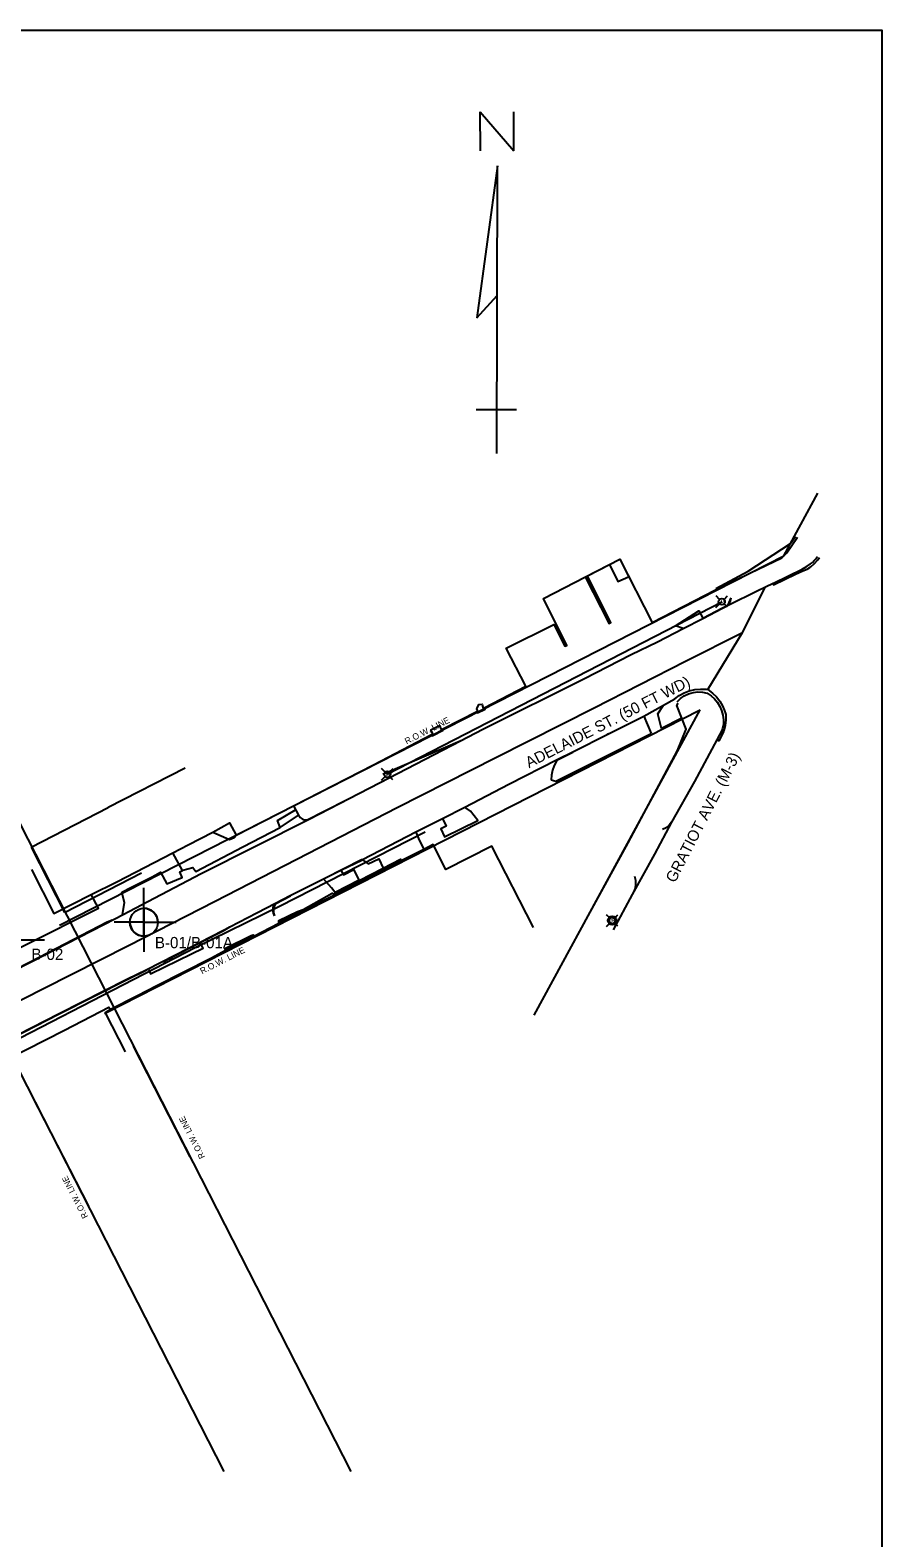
# Model space of a CAD drawing. Extents: x 19007.1 to 19038.2, y 21497.8 to 21516.9.
# Drawn here: x 19030.01 to 19036.42, y 21505.53 to 21516.88 of the extents above; entities that cross this region are included whole.
import ezdxf

# ---------------------------------------------------------------- set-up
doc = ezdxf.new("R2010")
doc.units = 0
for name, color, linetype in [('BORDER', 7, 'Continuous'), ('DETAIL_TEXT_DIMEN_PR', 7, 'Continuous'), ('G-ANNO-TTLB', 7, 'Continuous'), ('Level 14', 7, 'Continuous'), ('TYPICAL_TEXT_DIMEN_PR', 7, 'Continuous'), ('V-ANNO-TEXT', 7, 'Continuous'), ('V-BLDG-OTLN', 7, 'Continuous'), ('V-DEMO-PVMT', 7, 'Continuous'), ('V-PROP-RWAY', 7, 'Continuous'), ('V-PROP-RWAY-IDEN', 7, 'Continuous'), ('V-PVMT-CNTR', 7, 'Continuous'), ('V-PVMT-ROAD', 7, 'Continuous'), ('V-SITE-FENC', 7, 'Continuous'), ('V-SITE-STRS', 7, 'Continuous'), ('V-SITE-WALK', 7, 'Continuous'), ('V-UTIL-OVHD', 7, 'Continuous')]:
    doc.layers.add(name, color=color, linetype=linetype)

msp = doc.modelspace()

# ---------------------------------------------------------------- linework, layer by layer
at = {"layer": 'BORDER'}
for p, q in [((19033.402, 21515.972), (19033.399, 21516.267)), ((19033.399, 21516.267), (19033.653, 21515.971)), ((19033.653, 21515.971), (19033.652, 21516.267)), ((19033.528, 21515.86), (19033.374, 21514.715)), ((19033.523, 21513.693), (19033.528, 21515.86)), ((19033.374, 21514.715), (19033.526, 21514.882)), ((19033.673, 21514.021), (19033.368, 21514.022))]:
    msp.add_line(p, q, dxfattribs=at)
at = {"layer": 'G-ANNO-TTLB'}
msp.add_lwpolyline([(19036.423, 21497.766), (19007.08, 21497.766), (19007.08, 21516.881), (19036.423, 21516.881)], close=True, dxfattribs=at)
at = {"layer": 'Level 14'}
msp.add_circle((19034.393, 21510.176), 0.0328, dxfattribs=at)
at = {"layer": 'TYPICAL_TEXT_DIMEN_PR'}
for p, q in [((19030.866, 21510.163), (19030.866, 21510.421)), ((19030.866, 21510.163), (19030.642, 21510.163)), ((19030.866, 21510.163), (19030.866, 21509.939)), ((19030.866, 21510.163), (19031.11, 21510.163)), ((19029.874, 21510.031), (19030.118, 21510.031))]:
    msp.add_line(p, q, dxfattribs=at)
for points in [[(19030.866, 21510.268), (19030.866, 21510.163), (19030.971, 21510.163)], [(19030.866, 21510.057), (19030.866, 21510.163), (19030.76, 21510.163)]]:
    msp.add_lwpolyline(points, dxfattribs=at)
msp.add_circle((19030.866, 21510.163), 0.105, dxfattribs=at)
for start, end in [(0.0399, 90.0399), (180.0399, 270.0399)]:
    msp.add_arc((19030.866, 21510.163), 0.105, start, end, dxfattribs=at)
at = {"layer": 'V-BLDG-OTLN'}
for points in [[(19030.019, 21510.561), (19030.188, 21510.23), (19030.468, 21510.372), (19030.663, 21510.468), (19031.085, 21510.686), (19031.2, 21510.746), (19031.384, 21510.842), (19031.511, 21510.911), (19031.56, 21510.819), (19031.993, 21511.039), (19032.596, 21511.349), (19033.033, 21511.577), (19033.042, 21511.583), (19033.028, 21511.612), (19033.091, 21511.645), (19033.097, 21511.633), (19033.097, 21511.632), (19033.104, 21511.615), (19033.115, 21511.616), (19033.116, 21511.619), (19033.372, 21511.75), (19033.379, 21511.755), (19033.379, 21511.758), (19033.373, 21511.77), (19033.372, 21511.771), (19033.388, 21511.802), (19033.414, 21511.805), (19033.415, 21511.792), (19033.415, 21511.791), (19033.42, 21511.776), (19033.429, 21511.778), (19033.743, 21511.94), (19033.595, 21512.227), (19033.954, 21512.405), (19034.037, 21512.242), (19034.051, 21512.248), (19033.875, 21512.602), (19034.191, 21512.763), (19034.45, 21512.896), (19034.694, 21512.421), (19035.171, 21512.665)], [(19034.204, 21512.77), (19034.379, 21512.42), (19034.371, 21512.415), (19034.366, 21512.421), (19034.194, 21512.76)], [(19033.8, 21510.124), (19033.487, 21510.736), (19033.14, 21510.561), (19033.045, 21510.748), (19032.973, 21510.712), (19032.804, 21510.626), (19032.31, 21510.373), (19032.301, 21510.368), (19032.033, 21510.231), (19031.893, 21510.158), (19031.881, 21510.153), (19031.695, 21510.056), (19031.681, 21510.049), (19031.486, 21509.952), (19031.369, 21509.889), (19030.964, 21509.683), (19030.819, 21509.609), (19030.614, 21509.505), (19030.574, 21509.482), (19030.725, 21509.186)], [(19032.31, 21510.373), (19032.304, 21510.384), (19032.488, 21510.478), (19032.667, 21510.571), (19032.799, 21510.639), (19032.804, 21510.626)], [(19031.893, 21510.158), (19031.887, 21510.172), (19032.024, 21510.241), (19032.033, 21510.231)], [(19031.486, 21509.952), (19031.478, 21509.964), (19031.675, 21510.06), (19031.681, 21510.049)]]:
    msp.add_lwpolyline(points, dxfattribs=at)
at = {"layer": 'V-DEMO-PVMT'}
for points in [[(19028.097, 21508.889), (19028.362, 21509.022), (19028.49, 21509.087), (19028.616, 21509.152), (19029.3, 21509.501), (19030.016, 21509.866), (19030.652, 21510.19), (19030.704, 21510.219), (19030.996, 21510.373)], [(19028.108, 21509.039), (19028.353, 21509.164), (19028.617, 21509.301), (19029.241, 21509.619), (19029.408, 21509.702), (19029.965, 21509.988), (19030.523, 21510.268), (19030.468, 21510.372)], [(19030.701, 21510.39), (19030.772, 21510.426)], [(19030.704, 21510.219), (19030.719, 21510.312), (19030.701, 21510.39)], [(19028.555, 21509.213), (19028.585, 21509.187), (19028.628, 21509.161), (19029.299, 21509.504), (19030.015, 21509.868), (19030.59, 21510.166), (19030.626, 21510.182)], [(19028.305, 21508.482), (19028.718, 21508.689), (19029.272, 21508.987), (19029.505, 21509.106), (19030.229, 21509.475), (19030.738, 21509.734), (19030.887, 21509.807), (19031.202, 21509.968)], [(19030.903, 21509.805), (19030.917, 21509.774), (19031.224, 21509.925)], [(19031.01, 21509.866), (19031.203, 21509.965)], [(19029.262, 21508.846), (19029.258, 21508.867), (19029.265, 21508.958), (19029.277, 21508.987), (19029.507, 21509.104), (19030.228, 21509.473), (19030.74, 21509.732), (19030.888, 21509.804)]]:
    msp.add_lwpolyline(points, dxfattribs=at)
at = {"layer": 'V-PROP-RWAY'}
for p, q in [((19035.684, 21512.923), (19035.94, 21513.393)), ((19031.47, 21506.028), (19027.81, 21513.188)), ((19028.765, 21513.188), (19032.424, 21506.028)), ((19030.231, 21510.14), (19035.684, 21512.923)), ((19030.57, 21509.475), (19035.054, 21511.763)), ((19033.804, 21509.464), (19035.054, 21511.763)), ((19032.666, 21511.278), (19033.266, 21511.536)), ((19031.177, 21511.324), (19030.597, 21511.027)), ((19030.017, 21510.729), (19030.597, 21511.027)), ((19030.017, 21510.729), (19030.269, 21510.237)), ((19030.269, 21510.237), (19030.849, 21510.535)), ((19031.214, 21508.396), (19030.787, 21509.229)), ((19030.022, 21508.857), (19030.448, 21508.024))]:
    msp.add_line(p, q, dxfattribs=at)
at = {"layer": 'V-PVMT-CNTR'}
msp.add_lwpolyline([(19024.711, 21506.912), (19025.192, 21507.157), (19025.429, 21507.272), (19025.614, 21507.374), (19025.854, 21507.494), (19026.581, 21507.868), (19027.297, 21508.234), (19027.984, 21508.583), (19028.701, 21508.941), (19029.396, 21509.302), (19030.11, 21509.663), (19030.749, 21509.989), (19031.403, 21510.322), (19032.101, 21510.681), (19032.774, 21511.026), (19033.516, 21511.404), (19034.256, 21511.778), (19034.944, 21512.128), (19035.373, 21512.345)], dxfattribs=at)
at = {"layer": 'V-PVMT-ROAD'}
for points in [[(19030.996, 21510.373), (19031.298, 21510.531), (19032.11, 21510.939), (19032.412, 21511.094), (19032.639, 21511.213), (19033.187, 21511.496), (19033.424, 21511.619), (19034.179, 21511.995), (19034.536, 21512.178), (19034.733, 21512.275), (19034.927, 21512.374), (19035.075, 21512.451), (19035.271, 21512.553), (19035.484, 21512.658), (19035.546, 21512.689), (19035.604, 21512.716), (19035.607, 21512.705), (19035.773, 21512.784), (19035.829, 21512.81), (19035.861, 21512.823), (19035.88, 21512.834), (19035.892, 21512.843), (19035.914, 21512.862), (19035.941, 21512.893), (19035.953, 21512.91)], [(19034.191, 21512.763), (19034.367, 21512.412), (19034.382, 21512.42), (19034.207, 21512.771), (19034.373, 21512.856), (19034.436, 21512.728), (19034.516, 21512.764)], [(19035.606, 21512.717), (19035.823, 21512.821), (19035.854, 21512.84), (19035.886, 21512.861), (19035.901, 21512.873), (19035.914, 21512.887), (19035.923, 21512.897), (19035.938, 21512.918)], [(19035.074, 21512.453), (19035.265, 21512.552), (19035.289, 21512.606)], [(19035.113, 21511.915), (19035.373, 21512.345), (19035.546, 21512.689)], [(19035.272, 21512.556), (19035.284, 21512.583), (19035.289, 21512.606)], [(19031.202, 21509.968), (19031.289, 21510.013), (19031.461, 21510.101), (19031.514, 21510.128), (19031.716, 21510.234), (19031.857, 21510.307), (19031.968, 21510.364), (19032.219, 21510.49), (19032.229, 21510.494), (19032.504, 21510.635), (19032.512, 21510.635), (19032.915, 21510.843), (19033.115, 21510.945), (19033.283, 21511.029), (19033.613, 21511.202), (19033.979, 21511.388), (19034.096, 21511.447), (19034.364, 21511.582), (19034.354, 21511.577), (19034.63, 21511.716), (19034.78, 21511.797), (19034.863, 21511.845), (19034.897, 21511.87), (19034.934, 21511.891), (19034.973, 21511.906), (19035.014, 21511.916), (19035.057, 21511.919), (19035.099, 21511.917), (19035.113, 21511.915), (19035.148, 21511.889), (19035.178, 21511.861), (19035.203, 21511.828), (19035.223, 21511.793), (19035.235, 21511.763), (19035.248, 21511.728), (19035.249, 21511.686), (19035.244, 21511.644), (19035.233, 21511.602), (19035.232, 21511.601), (19035.195, 21511.529), (19035.183, 21511.537)], [(19034.881, 21511.822), (19034.906, 21511.848), (19034.935, 21511.868), (19034.967, 21511.884), (19035.001, 21511.894), (19035.037, 21511.898), (19035.072, 21511.896), (19035.107, 21511.889), (19035.107, 21511.889), (19035.137, 21511.868), (19035.164, 21511.845), (19035.186, 21511.818), (19035.204, 21511.787), (19035.215, 21511.757), (19035.226, 21511.722), (19035.231, 21511.688), (19035.23, 21511.655), (19035.223, 21511.622), (19035.218, 21511.607), (19035.011, 21511.223), (19034.84, 21510.916), (19034.712, 21510.675), (19034.544, 21510.372), (19034.401, 21510.107)], [(19034.354, 21511.577), (19034.631, 21511.714), (19034.687, 21511.585)], [(19034.917, 21511.699), (19034.764, 21511.623), (19034.735, 21511.732), (19034.78, 21511.797)], [(19033.033, 21511.577), (19033.038, 21511.567), (19033.12, 21511.61)], [(19033.98, 21511.386), (19034.096, 21511.445)], [(19031.893, 21510.876), (19031.871, 21510.928), (19032.007, 21511.01)], [(19031.993, 21511.039), (19032.03, 21510.97), (19032.032, 21510.966), (19032.043, 21510.952), (19032.057, 21510.941), (19032.074, 21510.935), (19032.092, 21510.935), (19032.1, 21510.937), (19032.219, 21510.996), (19032.412, 21511.094)], [(19033.115, 21510.945), (19033.143, 21510.887), (19033.101, 21510.867), (19033.13, 21510.806), (19033.38, 21510.929), (19033.326, 21510.999), (19033.292, 21511.022), (19033.283, 21511.029)], [(19031.159, 21510.556), (19031.234, 21510.575), (19031.258, 21510.545), (19031.611, 21510.732), (19031.893, 21510.876), (19032.03, 21510.97)], [(19034.84, 21510.916), (19034.821, 21510.894), (19034.798, 21510.875), (19034.772, 21510.862)], [(19031.384, 21510.842), (19031.51, 21510.786), (19031.545, 21510.8), (19031.56, 21510.819)], [(19032.916, 21510.836), (19032.934, 21510.793), (19032.973, 21510.712)], [(19030.928, 21510.506), (19030.992, 21510.539), (19031.038, 21510.451), (19031.153, 21510.501), (19031.136, 21510.543), (19031.157, 21510.553), (19031.085, 21510.686)], [(19032.229, 21510.494), (19032.348, 21510.554), (19032.513, 21510.633)], [(19032.306, 21510.389), (19032.486, 21510.482), (19032.448, 21510.56)], [(19032.348, 21510.554), (19032.369, 21510.521), (19032.448, 21510.56)], [(19032.513, 21510.633), (19032.556, 21510.602), (19032.635, 21510.64), (19032.667, 21510.571)], [(19030.772, 21510.426), (19030.928, 21510.506)], [(19032.305, 21510.39), (19032.278, 21510.422), (19032.219, 21510.49)], [(19034.561, 21510.511), (19034.568, 21510.481), (19034.569, 21510.449), (19034.565, 21510.419), (19034.554, 21510.389), (19034.544, 21510.372)], [(19031.484, 21509.951), (19031.476, 21509.965), (19031.673, 21510.064), (19031.689, 21510.069), (19031.695, 21510.056), (19031.881, 21510.153), (19031.883, 21510.175), (19032.022, 21510.243), (19032.065, 21510.26), (19032.284, 21510.381), (19032.301, 21510.368)], [(19031.851, 21510.211), (19031.844, 21510.234), (19031.844, 21510.259), (19031.849, 21510.282), (19031.86, 21510.304), (19031.86, 21510.305), (19031.969, 21510.362)], [(19031.849, 21510.21), (19031.841, 21510.231), (19031.837, 21510.253), (19031.84, 21510.275), (19031.849, 21510.296), (19031.857, 21510.307)], [(19032.034, 21510.228), (19031.994, 21510.208)], [(19031.203, 21509.965), (19031.291, 21510.01), (19031.463, 21510.099), (19031.514, 21510.128)], [(19031.224, 21509.925), (19031.313, 21509.969), (19031.291, 21510.01)]]:
    msp.add_lwpolyline(points, dxfattribs=at)
at = {"layer": 'V-SITE-FENC'}
msp.add_lwpolyline([(19035.173, 21512.675), (19035.417, 21512.806), (19035.735, 21513.014), (19035.773, 21513.069)], dxfattribs=at)
at = {"layer": 'V-SITE-STRS'}
for points in [[(19034.437, 21512.732), (19034.374, 21512.857)], [(19034.45, 21512.896), (19034.516, 21512.768)], [(19034.723, 21512.436), (19034.767, 21512.458)], [(19033.379, 21511.755), (19033.379, 21511.758), (19033.373, 21511.77), (19033.372, 21511.771), (19033.388, 21511.802), (19033.414, 21511.805), (19033.415, 21511.792), (19033.415, 21511.791), (19033.42, 21511.776), (19033.424, 21511.776), (19033.428, 21511.777)], [(19033.372, 21511.75), (19033.377, 21511.739), (19033.435, 21511.767), (19033.429, 21511.778)], [(19033.374, 21511.75), (19033.379, 21511.741), (19033.434, 21511.767), (19033.428, 21511.778)], [(19033.042, 21511.583), (19033.04, 21511.588), (19033.034, 21511.6), (19033.033, 21511.601), (19033.028, 21511.612), (19033.091, 21511.645), (19033.097, 21511.633), (19033.097, 21511.632), (19033.104, 21511.615), (19033.115, 21511.616)], [(19033.034, 21511.575), (19033.038, 21511.568), (19033.118, 21511.61), (19033.115, 21511.616)]]:
    msp.add_lwpolyline(points, dxfattribs=at)
at = {"layer": 'V-SITE-WALK'}
for points in [[(19035.172, 21512.665), (19035.434, 21512.793), (19035.669, 21512.906), (19035.707, 21512.944), (19035.789, 21513.063)], [(19034.927, 21512.374), (19034.869, 21512.394), (19035.045, 21512.509), (19035.074, 21512.453)], [(19034.212, 21510.212), (19034.512, 21510.762), (19034.885, 21511.457), (19034.95, 21511.618), (19034.917, 21511.699), (19034.879, 21511.796), (19034.889, 21511.813)], [(19033.934, 21511.235), (19033.969, 21511.226), (19034.43, 21511.456), (19034.687, 21511.585)], [(19033.98, 21511.386), (19033.974, 21511.376), (19033.956, 21511.343), (19033.943, 21511.307), (19033.936, 21511.27), (19033.934, 21511.235)], [(19029.263, 21508.844), (19029.408, 21508.928), (19029.551, 21508.987), (19030.268, 21509.35), (19030.603, 21509.523), (19030.614, 21509.505)]]:
    msp.add_lwpolyline(points, dxfattribs=at)
at = {"layer": 'V-UTIL-OVHD'}
for p, q in [((19035.201, 21512.594), (19035.175, 21512.62)), ((19035.235, 21512.594), (19035.261, 21512.62)), ((19035.174, 21512.533), (19035.201, 21512.56)), ((19035.26, 21512.535), (19035.235, 21512.56)), ((19032.683, 21511.294), (19032.656, 21511.32)), ((19032.656, 21511.233), (19032.683, 21511.26)), ((19032.716, 21511.294), (19032.742, 21511.32)), ((19032.741, 21511.235), (19032.716, 21511.26)), ((19034.376, 21510.193), (19034.35, 21510.219)), ((19034.41, 21510.193), (19034.436, 21510.219)), ((19034.35, 21510.132), (19034.376, 21510.159)), ((19034.435, 21510.134), (19034.41, 21510.159))]:
    msp.add_line(p, q, dxfattribs=at)
for points in [[(19032.699, 21511.277), (19035.218, 21512.577)], [(19026.038, 21507.219), (19026.804, 21507.669), (19027.068, 21507.797), (19027.741, 21508.152), (19029.314, 21508.974), (19031.251, 21509.972), (19031.886, 21510.285), (19032.984, 21510.845)]]:
    msp.add_lwpolyline(points, dxfattribs=at)
for centre in [(19035.218, 21512.577), (19032.699, 21511.277), (19034.393, 21510.176)]:
    msp.add_circle(centre, 0.0239, dxfattribs=at)

# ---------------------------------------------------------------- texts
at = {"layer": 'DETAIL_TEXT_DIMEN_PR'}
for s, p in [('B-01/B-01A', (19030.949, 21509.967)), ('B-02', (19030.019, 21509.879))]:
    msp.add_text(s, height=0.085, rotation=0.0399, dxfattribs=at).set_placement(p)
at = {"layer": 'V-ANNO-TEXT'}
for s, rotation, p in [('ADELAIDE ST. (50 FT WD)', 27.0313, (19033.766, 21511.322)), ('GRATIOT AVE. (M-3)', 62.8066, (19034.865, 21510.454))]:
    msp.add_text(s, height=0.08361, rotation=rotation, dxfattribs=at).set_placement(p)
at = {"layer": 'V-PROP-RWAY-IDEN'}
for height, rotation, p in [(0.04778, 27.0313, (19032.845, 21511.501)), (0.04778, 27.0313, (19031.304, 21509.77)), (0.04535, 117.1686, (19031.328, 21508.396)), (0.04535, 117.1686, (19030.447, 21507.946))]:
    msp.add_text('R.O.W. LINE', height=height, rotation=rotation, dxfattribs=at).set_placement(p)
at = {"layer": 'V-UTIL-OVHD'}
for s, height, p in [('M', 0.0239, (19035.209, 21512.565)), ('M', 0.0239, (19032.69, 21511.265)), ('LB', 0.0275, (19034.371, 21510.162)), ('M', 0.0239, (19034.384, 21510.164))]:
    msp.add_text(s, height=height, rotation=360, dxfattribs=at).set_placement(p)

doc.saveas('drawing.dxf')
